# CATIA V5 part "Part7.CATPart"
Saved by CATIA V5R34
Part number: Part7
Bounding box of the stored display mesh (mm): x -105 to 105, y 0 to 3, z -100 to 100
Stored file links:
  C:\Users\Apolinar\Desktop\cnc\Part7.CATPart
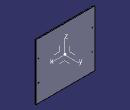
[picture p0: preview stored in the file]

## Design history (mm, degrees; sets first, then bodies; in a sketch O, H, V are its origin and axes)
AxisSystem1: origin (0, 0, 0), X (1, 0, 0), Y (0, 1, 0), Z (0, 0, 1)
Body1 (main body)
  Sketch1 on ZX plane of AxisSystem1, origin (0, 0, 0), H (0, 0, 1), V (1, 0, 0)
    line L1 (100, 105) -> (100, -105)
    line L2 (100, -105) -> (-100, -105)
    line L3 (-100, -105) -> (-100, 105)
    line L4 (-100, 105) -> (100, 105)
    circle A1 centre (-37.5, 95.5835) radius 1.5
    point P5 (-37.5, 95.5835)
    point P6 (37.5, 95.5835)
    circle A2 centre (37.5, 95.5835) radius 1.5
    point P7 (-37.5, -95.5835)
    circle A3 centre (-37.5, -95.5835) radius 1.5
    circle A4 centre (37.5, -95.5835) radius 1.5
    length L4 = 200
    length L1 = 210
    radius A1 = 1.5
    distance P5 P6 = 75
    distance P5 P7 = 191.167
    vertical: L1 V, L3 V
    horizontal: L2 H, L4 H
    equidistance: L1 L3 O, L2 L4 O
    symmetry: A1 A2 V, A1 A3 H, A2 A4 H
  Pad1: profile Sketch1, direction (0, 1, 0), length 3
